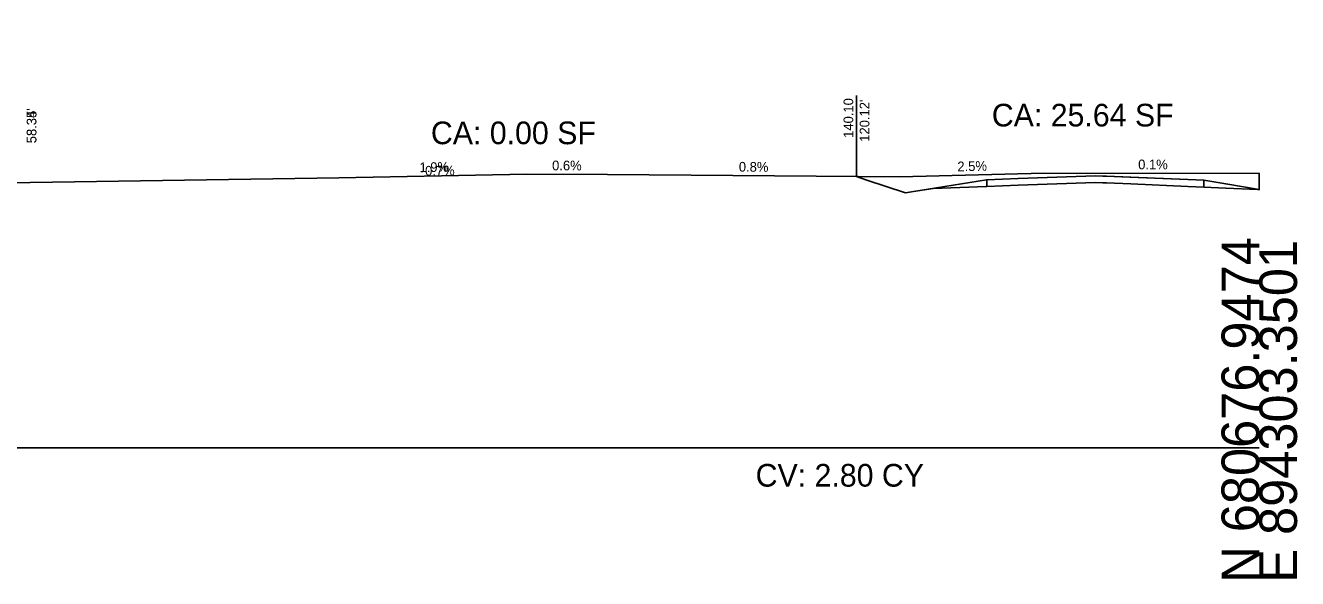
# Model space of a CAD drawing. Extents: x -26 to 4303, y -13 to 10775.
# Drawn here: x 1208.5 to 1302.8, y 6990.3 to 7031.3 of the extents above; entities that cross this region are included whole.
import ezdxf

# ---------------------------------------------------------------- set-up
doc = ezdxf.new("R2010")
doc.units = 0
for name, color, linetype in [('CONST_LV3', 7, 'Continuous'), ('DTM_P_FINISHED_GRADE', 7, 'Continuous'), ('DTM_X_GROUND', 7, 'Continuous'), ('X_PROFILES_1', 7, 'Continuous'), ('XS_CELL', 7, 'Continuous'), ('XS_M_SHAPES_EARTHWORK', 7, 'Continuous'), ('XS_P_DR_GRAVEL', 7, 'Continuous'), ('XS_P_GROUND', 7, 'Continuous'), ('XS_P_TX_CLEARZONE', 7, 'Continuous'), ('XS_P_TX_FS_BS', 7, 'Continuous'), ('XS_SHEET_EW_TX_AREA', 7, 'Continuous'), ('XS_SHEET_EW_TX_VOLUME', 7, 'Continuous')]:
    doc.layers.add(name, color=color, linetype=linetype)

msp = doc.modelspace()

# ---------------------------------------------------------------- linework, layer by layer
at = {"layer": 'CONST_LV3'}
msp.add_lwpolyline([(1279.796, 7019.871), (1282.118, 7019.956), (1287.847, 7020.167), (1288.408, 7020.143), (1288.638, 7020.133), (1290.402, 7020.058), (1294.694, 7019.875), (1295.899, 7019.823)], dxfattribs=at)
at = {"layer": 'DTM_P_FINISHED_GRADE'}
msp.add_lwpolyline([(1279.796, 7019.871), (1282.125, 7019.957), (1287.847, 7020.167), (1288.408, 7020.143), (1288.638, 7020.133), (1288.668, 7020.132), (1290.475, 7020.055), (1294.694, 7019.875), (1295.899, 7019.823)], dxfattribs=at)
at = {"layer": 'DTM_X_GROUND'}
msp.add_lwpolyline([(1000, 7031.302), (1001.603, 7031.182), (1022.191, 7022.251), (1033.153, 7016.884), (1037.339, 7015.992), (1066.759, 7011.226), (1079.976, 7011.364), (1102.58, 7011.905), (1149.985, 7011.053), (1150.069, 7011.049), (1150.149, 7011.048), (1152.173, 7011.009), (1154.677, 7011.4), (1171.881, 7015.145), (1192.056, 7019.573), (1202.28, 7019.562), (1231.744, 7020.006), (1245.674, 7020.278), (1251.654, 7020.244), (1273.339, 7020.079), (1284.055, 7020.346), (1300, 7020.335)], dxfattribs=at)
at = {"layer": 'XS_CELL'}
msp.add_line((1150, 7000), (1300, 7000), dxfattribs=at)
at = {"layer": 'XS_P_DR_GRAVEL'}
for points in [[(1279.796, 7019.871), (1279.796, 7019.371), (1282.125, 7019.457), (1287.847, 7019.667), (1288.408, 7019.643), (1288.638, 7019.633), (1288.668, 7019.632), (1290.475, 7019.555), (1294.694, 7019.375), (1295.899, 7019.323), (1295.899, 7019.823), (1294.694, 7019.875), (1290.475, 7020.055), (1288.668, 7020.132), (1288.638, 7020.133), (1288.408, 7020.143), (1287.847, 7020.167), (1282.125, 7019.957), (1279.796, 7019.871)], [(1275.823, 7019.225), (1279.765, 7019.37), (1279.796, 7019.371)], [(1295.899, 7019.323), (1297.511, 7019.254), (1299.871, 7019.153)]]:
    msp.add_lwpolyline(points, dxfattribs=at)
at = {"layer": 'XS_P_GROUND'}
for points in [[(1270.124, 7020.104), (1270.892, 7019.847), (1273.758, 7018.889), (1274.199, 7018.961), (1279.765, 7019.866), (1279.796, 7019.871)], [(1295.899, 7019.823), (1297.511, 7019.551), (1300, 7019.132)]]:
    msp.add_lwpolyline(points, dxfattribs=at)
at = {"layer": 'XS_P_TX_CLEARZONE'}
msp.add_line((1270.124, 7020.104), (1270.124, 7026.104), dxfattribs=at)
msp.add_line((1270.124, 7020.104), (1270.124, 7026.104), dxfattribs=at)
msp.add_line((1270.124, 7020.104), (1270.124, 7026.104), dxfattribs=at)
at = {"layer": 'XS_SHEET_EW_TX_AREA'}
msp.add_lwpolyline([(1270.124, 7020.104), (1273.339, 7020.079), (1284.055, 7020.346), (1300, 7020.335), (1300, 7019.132), (1299.871, 7019.153), (1297.511, 7019.254), (1295.899, 7019.323), (1294.694, 7019.375), (1290.475, 7019.555), (1288.668, 7019.632), (1288.638, 7019.633), (1288.408, 7019.643), (1287.847, 7019.667), (1282.125, 7019.457), (1279.796, 7019.371), (1279.765, 7019.37), (1275.823, 7019.225), (1274.199, 7018.961), (1273.758, 7018.889), (1270.892, 7019.847)], close=True, dxfattribs=at)

# ---------------------------------------------------------------- texts
at = {"layer": 'X_PROFILES_1'}
msp.add_text('X', height=0.12, dxfattribs=at).set_placement((1270.084, 7020.044))
at = {"layer": 'XS_CELL'}
for s, p in [('N 680676.9474', (1300, 6990)), ('E 894303.3501', (1302.8, 6990))]:
    msp.add_text(s, height=2.8, rotation=90, dxfattribs=at).set_placement(p)
at = {"layer": 'XS_M_SHAPES_EARTHWORK'}
msp.add_text('CV: 2.80 CY', height=1.68, dxfattribs=at).set_placement((1262.647, 6997.12))
at = {"layer": 'XS_P_TX_CLEARZONE'}
for s, p in [('140.10', (1269.884, 7022.97)), ('140.10', (1269.884, 7022.97)), ('140.10', (1269.884, 7022.97)), ("120.12'", (1271.084, 7022.681)), ("120.12'", (1271.084, 7022.681)), ("120.12'", (1271.084, 7022.681)), ("58.34'", (1209.297, 7022.568)), ("58.34'", (1209.297, 7022.568)), ("58.35'", (1209.306, 7022.571)), ("58.35'", (1209.306, 7022.571))]:
    msp.add_text(s, height=0.72, rotation=90, dxfattribs=at).set_placement(p)
at = {"layer": 'XS_P_TX_FS_BS'}
for s, rotation, p in [('1.9%', 1.11671, (1237.721, 7020.423)), ('0.7%', 0.41788, (1238.131, 7020.17)), ('0.6%', 359.68278, (1247.547, 7020.567)), ('0.8%', 359.56336, (1261.397, 7020.47)), ('2.5%', 1.42559, (1277.616, 7020.486)), ('0.1%', 359.96264, (1291.017, 7020.641))]:
    msp.add_text(s, height=0.72, rotation=rotation, dxfattribs=at).set_placement(p)
at = {"layer": 'XS_SHEET_EW_TX_VOLUME'}
for s, p in [('CA: 25.64 SF', (1280.162, 7023.814)), ('CA: 0.00 SF', (1238.561, 7022.5))]:
    msp.add_text(s, height=1.68, dxfattribs=at).set_placement(p)

doc.saveas('drawing.dxf')
